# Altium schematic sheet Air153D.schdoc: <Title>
size 419 x 266 mm; Name: SIZEB; Symbol: SIZEB; Device: SIZEB; Drawn By: <Drawn By>; Checked By: <Checked By>; QC By: <QC By>; Released By: <Released By>; Drawn Date: <Drawn Date>; Checked Date: <Checked Date>; QC Date: <QC Date>; Release Date: <Release Date>; Company Name: <Company Name>; Code: <Code>; Sheet Size: B; Drawing Number: <Drawing Number>; Revision: <Revision>; Scale: <Scale>; Sheet Number: 1; Number of Sheets: 1
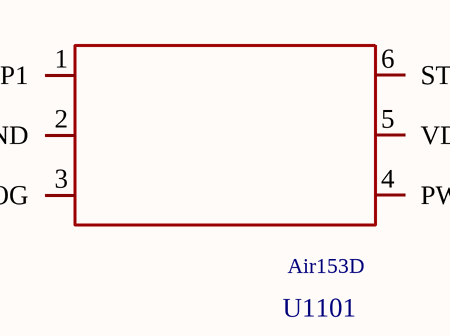
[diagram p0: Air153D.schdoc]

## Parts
U1101  value Air153D  (hidden comment: Kicad元件库_看门狗_OTPMCU)

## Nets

Not connected (* = marked no-connect by the designer): U1101 1(STRAP1) 2(GND) 3(WTDOG) 4(PWR_OFF) 5(VDD) 6(STRAP6)

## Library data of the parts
U1101 = AIR153D: Origin_Footprint: SOT-23-6; Convert to PCB: yes; Origin Footprint: SOT-23-6_L2.9-W1.6-P0.95-LS2.8-BR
